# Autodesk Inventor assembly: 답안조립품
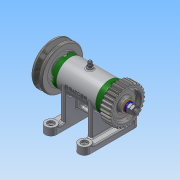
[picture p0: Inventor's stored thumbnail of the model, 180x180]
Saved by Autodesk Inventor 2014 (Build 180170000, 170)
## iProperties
Created: 2015-11
Part Number: 답안조립품
Document SubType Name: Assembly
Designer: 103-25
Author: 103-25
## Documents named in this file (16)
- C:\Users\103-25\Desktop\451110V1020\답안조립품.iam
- C:\Users\103-25\Desktop\451110V1020\본체.ipt
- C:\Users\103-25\Desktop\451110V1020\V벨트풀리.ipt
- C:\Users\103-25\Desktop\451110V1020\너트 M 8.ipt
- C:\Users\103-25\Desktop\451110V1020\니플 M 6 x 0.75.ipt
- C:\Users\103-25\Desktop\451110V1020\베어링 15 x 32 x 9.ipt
- C:\Users\103-25\Desktop\451110V1020\볼트 M 6 x 8.ipt
- C:\Users\103-25\Desktop\451110V1020\볼트 M4 x 12.ipt
- C:\Users\103-25\Desktop\451110V1020\스퍼기어.ipt
- C:\Users\103-25\Desktop\451110V1020\스프링와셔 8.ipt
- C:\Users\103-25\Desktop\451110V1020\오일 실 15 25 7.ipt
- C:\Users\103-25\Desktop\451110V1020\와셔 6x11.5.ipt
- C:\Users\103-25\Desktop\451110V1020\와셔 8x17.ipt
- C:\Users\103-25\Desktop\451110V1020\축.ipt
- C:\Users\103-25\Desktop\451110V1020\커버.ipt
- C:\Users\103-25\Desktop\451110V1020\키 3 x 3 x 12.ipt
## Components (11 placed, 3 different names)
1. V벨트풀리:1 — 각도:4
2. KS B 2023 6002 - 15 x 32 x 9:1
3. KS B 2023 6002 - 15 x 32 x 9:2
4. ISO 4762 M4 x 12:2
5. ISO 4762 M4 x 12:3
6. ISO 4762 M4 x 12:4
7. ISO 4762 M4 x 12:5
8. ISO 4762 M4 x 12:1
9. ISO 4762 M4 x 12:6
10. ISO 4762 M4 x 12:7
11. ISO 4762 M4 x 12:8
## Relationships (1: Angle 1)
- 각도:4 [Angle]: V벨트풀리:1
